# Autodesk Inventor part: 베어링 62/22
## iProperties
Created: 2009-02
Part Number: 베어링 62/22
Material: 강, 연강
Description: 깊은 그루브 볼 베어링
Document SubType Name: Modeling
Standard: KS B 2023
Designer: KYOUNG IL JANG
Standards Organization: KS
Language: ko-KR
Size Designation: 62/22 - 22 x 50 x 14
Categories: <MemberInstance><Categories><Category DisplayName="샤프트 부품" InternalName="7f7aeb1f-a693-4053-b835-cee3144e0d98" Mnemonic="SHFT"><Category DisplayName="베어링" Inter
Density: 7.86 g/cm^3
Mass: 117.523 g
Surface Area: 96.9171 cm^2
Volume: 14.952 cm^3
IsCustomPart: 0
Author: KYOUNG IL JANG
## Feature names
1. IDS_ARRAYBALL[SIMPL:T] [Circular Pattern]
